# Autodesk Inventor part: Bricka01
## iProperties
Created: 2001-12
Part Number: Bricka01
Material: Steel, Mild
Document SubType Name: Modeling
Designer: Tobben
Control State: 0
Master: False
Checked Out: False
Shininess: 64.0
Length Units: 11269
Angle Units: 11279
Time Units: 11290
Mass Units: 11283
Length Display Precision: 3
Angle Display Precision: 2
Density: 0.0
Volumn: 0.0
Area: 0.0
PropertySet Name: Model Information
Author: Tobben
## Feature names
1. Extrusion1
2. Hole1
3. Fillet1
4. Extrusion2
